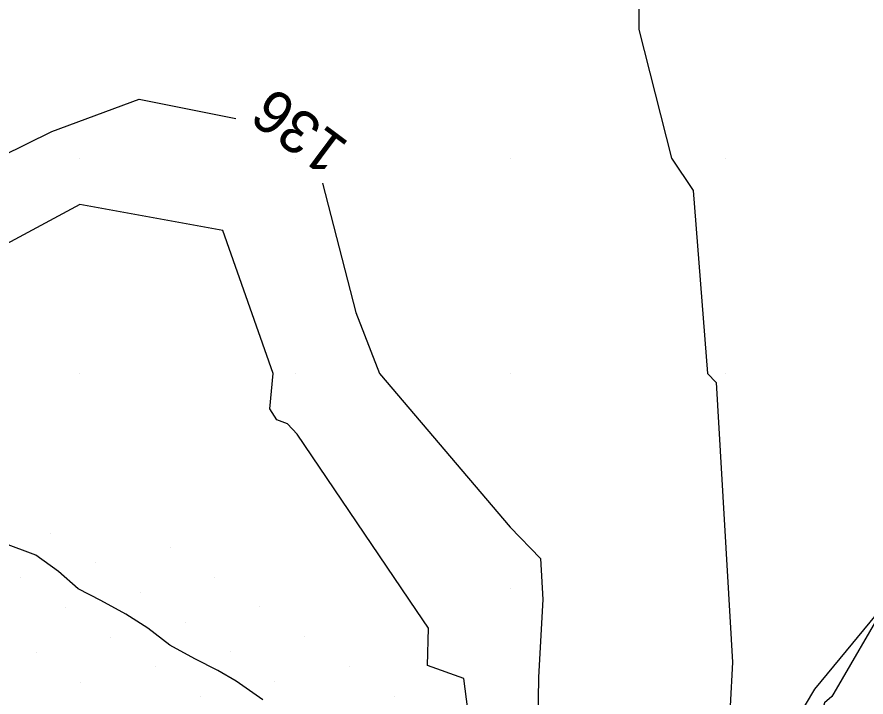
# Model space of a CAD drawing. Extents: x 2354170 to 2357230, y 866100 to 868290.
# Drawn here: x 2354917.05 to 2354956.5, y 867634.99 to 867666.58 of the extents above; entities that cross this region are included whole.
import ezdxf

# ---------------------------------------------------------------- set-up
doc = ezdxf.new("R2010")
doc.units = 0
for name, color, linetype in [('Default', 7, 'Continuous'), ('DTM Contours Minor', 7, 'Continuous'), ('Exist DTM QL2 LIDAR Elevation Point', 7, 'Continuous'), ('Exist DTM Scan Elevation Point', 7, 'Continuous'), ('PH Exist DTM Breakline', 7, 'Continuous')]:
    doc.layers.add(name, color=color, linetype=linetype)

msp = doc.modelspace()

# ---------------------------------------------------------------- linework, layer by layer
at = {"layer": 'Default'}
for points in [[(2354945.961, 867670.018), (2354945.942, 867665.99), (2354947.461, 867660.018), (2354948.473, 867658.52), (2354949.136, 867650.018), (2354949.543, 867649.591), (2354950.299, 867636.613), (2354950.188, 867634.569), (2354950.786, 867634.078), (2354953.261, 867633.904), (2354952.469, 867630.928), (2354952.242, 867630.108), (2354952.021, 867629.326), (2354950.637, 867627.548), (2354950.348, 867627.931), (2354950.125, 867627.118), (2354949.987, 867626.127), (2354949.905, 867625.486), (2354950.29, 867624.231), (2354950.545, 867621.728), (2354952.165, 867616.309), (2354952.964, 867615.923), (2354956.682, 867611.338)], [(2354906.967, 867655.493), (2354918.665, 867661.251), (2354922.718, 867662.766), (2354927.215, 867661.857)], [(2354931.239, 867658.856), (2354932.8, 867652.848), (2354933.899, 867650.018), (2354939.971, 867642.885), (2354941.369, 867641.417), (2354941.479, 867639.521), (2354941.284, 867635.908), (2354941.231, 867632.781)], [(2354928.467, 867634.851), (2354927.227, 867635.728), (2354926.376, 867636.221), (2354925.316, 867636.756), (2354924.153, 867637.391), (2354923.12, 867638.179), (2354922.108, 867638.831), (2354920.95, 867639.475), (2354919.887, 867640.006), (2354918.973, 867640.823), (2354917.927, 867641.574), (2354916.388, 867642.154)], [(2354957.437, 867639.353), (2354955.011, 867635.172), (2354954.91, 867635.012), (2354954.579, 867634.715), (2354953.598, 867631.033), (2354953.178, 867629.515), (2354953.077, 867629.347), (2354950.784, 867626.406), (2354951.253, 867621.803), (2354952.74, 867616.828), (2354953.953, 867616.242), (2354957.359, 867612.042)]]:
    msp.add_lwpolyline(points, dxfattribs=at)
at = {"layer": 'DTM Contours Minor'}
msp.add_lwpolyline([(2354946.421, 867626.83), (2354944.832, 867627.87), (2354944.543, 867628.043), (2354942.745, 867629.246), (2354940.939, 867630.41), (2354940.622, 867630.569), (2354938.807, 867632.016), (2354938.657, 867632.13), (2354938.238, 867632.618), (2354937.808, 867635.85), (2354936.122, 867636.458), (2354936.172, 867638.186), (2354935.606, 867639.003), (2354930.073, 867647.198), (2354929.616, 867647.679), (2354929.121, 867647.861), (2354928.792, 867648.379), (2354928.954, 867650.018), (2354926.612, 867656.66), (2354919.97, 867657.859), (2354910.92, 867653.005)], dxfattribs=at)
at = {"layer": 'Exist DTM QL2 LIDAR Elevation Point'}
for p, q in [((2354919.97, 867660.018), (2354919.97, 867660.018)), ((2354929.97, 867660.018), (2354929.97, 867660.018)), ((2354939.971, 867660.018), (2354939.971, 867660.018)), ((2354949.971, 867660.018), (2354949.971, 867660.018)), ((2354919.97, 867650.018), (2354919.97, 867650.018)), ((2354929.97, 867650.018), (2354929.97, 867650.018)), ((2354939.971, 867650.018), (2354939.971, 867650.018)), ((2354949.971, 867650.018), (2354949.971, 867650.018)), ((2354939.971, 867640.018), (2354939.971, 867640.018))]:
    msp.add_line(p, q, dxfattribs=at)
at = {"layer": 'Exist DTM Scan Elevation Point'}
for p, q in [((2354918.61, 867642.606), (2354918.61, 867642.606)), ((2354924.16, 867641.933), (2354924.16, 867641.933)), ((2354920.695, 867641.227), (2354920.695, 867641.227)), ((2354926.244, 867640.553), (2354926.244, 867640.553)), ((2354917.231, 867640.522), (2354917.231, 867640.522)), ((2354922.78, 867639.848), (2354922.78, 867639.848)), ((2354919.316, 867639.142), (2354919.316, 867639.142)), ((2354928.329, 867639.174), (2354928.329, 867639.174)), ((2354924.865, 867638.468), (2354924.865, 867638.468)), ((2354930.414, 867637.794), (2354930.414, 867637.794)), ((2354921.401, 867637.763), (2354921.401, 867637.763)), ((2354917.936, 867637.057), (2354917.936, 867637.057)), ((2354926.95, 867637.089), (2354926.95, 867637.089)), ((2354923.486, 867636.383), (2354923.486, 867636.383)), ((2354932.499, 867636.415), (2354932.499, 867636.415)), ((2354920.021, 867635.678), (2354920.021, 867635.678)), ((2354929.035, 867635.709), (2354929.035, 867635.709)), ((2354934.584, 867635.035), (2354934.584, 867635.035)), ((2354925.571, 867635.004), (2354925.571, 867635.004))]:
    msp.add_line(p, q, dxfattribs=at)
at = {"layer": 'PH Exist DTM Breakline'}
msp.add_lwpolyline([(2354950.702, 867629.187), (2354951.43, 867630.832), (2354954.125, 867635.352), (2354957.876, 867639.883), (2354963.714, 867643.781), (2354969.11, 867646.734), (2354972.897, 867648.077), (2354977.351, 867648.954), (2354983.334, 867649.185), (2354988.141, 867648.209), (2354992.972, 867646.52), (2355001.969, 867642.971), (2355023.225, 867633.369), (2355050.188, 867621.573)], dxfattribs=at)

# ---------------------------------------------------------------- texts
at = {"layer": 'Default'}
msp.add_text('136', height=2, rotation=143.2906, dxfattribs=at).set_placement((2354932.547, 867660.702))

doc.saveas('drawing.dxf')
